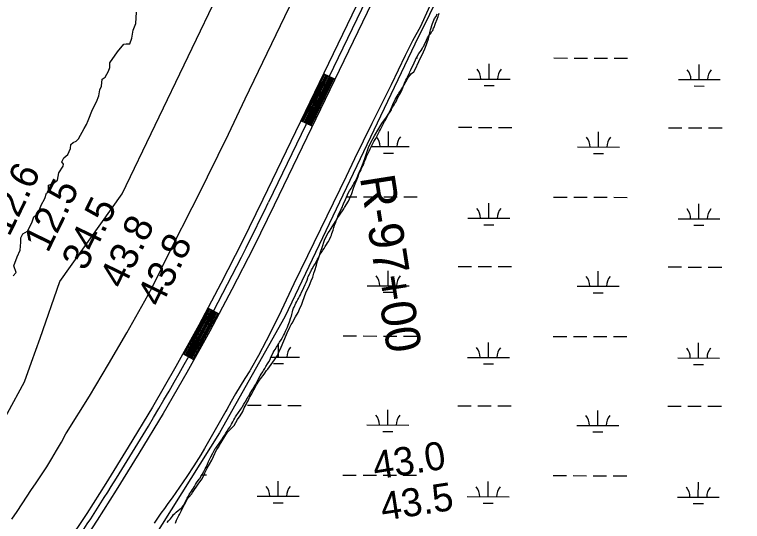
# Model space of a CAD drawing. Extents: x 3180038 to 3217926, y 922069 to 947485.
# Drawn here: x 3189237 to 3190976, y 935548 to 936760 of the extents above; entities that cross this region are included whole.
import ezdxf

# ---------------------------------------------------------------- set-up
doc = ezdxf.new("R2010")
doc.units = 0
for name, color, linetype in [('V-LEVE-TOET', 7, 'Continuous'), ('V-RIVR-EDGE', 7, 'Continuous'), ('V-RIVR-RANG', 7, 'Continuous'), ('V-RIVR-RANG-IDEN', 7, 'Continuous'), ('V-ROAD-CNTR', 7, 'Continuous'), ('V-SITE-VEGE', 7, 'Continuous'), ('V-TOPO-SHOR', 7, 'Continuous'), ('V-WETL-SWMP', 7, 'Continuous')]:
    doc.layers.add(name, color=color, linetype=linetype)

msp = doc.modelspace()

# ---------------------------------------------------------------- linework, layer by layer
at = {"layer": 'V-LEVE-TOET'}
for points in [[(3189230.6, 935554.3), (3189243.1, 935572.3), (3189255.3, 935590.5), (3189267.1, 935608.9), (3189275.5, 935622.2), (3189275.5, 935622.2), (3189288.5, 935641), (3189301.2, 935660), (3189313.5, 935679.2), (3189325.6, 935698.6), (3189337.2, 935718.2), (3189348.6, 935738.1), (3189359.6, 935758.1), (3189360.7, 935760.2), (3189360.7, 935760.2), (3189415.5, 935847.9), (3189461.5, 935924), (3189461.5, 935924), (3189505.4, 935999.3), (3189548, 936075.4), (3189565.3, 936107.2), (3189565.3, 936107.2), (3189612.4, 936203.2), (3189661.1, 936298.5), (3189673.2, 936321.5), (3189673.2, 936321.5), (3189747.7, 936474), (3189787.7, 936558.6), (3189787.7, 936558.6), (3189903.7, 936800.3)], [(3190229, 936780.3), (3190216.9, 936754.5), (3190206.3, 936731.3), (3190206.3, 936731.3), (3190187.9, 936696.8), (3190170.1, 936662.1), (3190152.9, 936627), (3190136.3, 936591.6), (3190132.9, 936584.2), (3190132.9, 936584.2), (3190090.2, 936499.8), (3190049.1, 936414.6), (3190029.4, 936372.6), (3190029.4, 936372.6), (3189936.3, 936183.2), (3189936.3, 936183.2), (3189904.1, 936116.6), (3189873.9, 936051.6), (3189873.9, 936051.6), (3189856.3, 936015.6), (3189838.1, 935980), (3189819.2, 935944.7), (3189799.8, 935909.7), (3189799, 935908.3), (3189799, 935908.3), (3189787.3, 935890.2), (3189776, 935871.9), (3189765, 935853.4), (3189754.3, 935834.7), (3189743.9, 935815.8), (3189741.9, 935811.9), (3189741.9, 935811.9), (3189690.7, 935723.1), (3189681.6, 935707.6), (3189681.6, 935707.6), (3189665.1, 935681.6), (3189648.3, 935655.8), (3189630.9, 935630.3), (3189613.2, 935605.1), (3189603.2, 935591.3), (3189603.2, 935591.3), (3189594.7, 935579.7), (3189586.4, 935568), (3189578.3, 935556.2), (3189570.5, 935544.2)]]:
    msp.add_lwpolyline(points, dxfattribs=at)
at = {"layer": 'V-RIVR-EDGE'}
for points in [[(3189383.8, 936457.4), (3189389.6, 936463.1), (3189403.1, 936487.5), (3189408.8, 936496.8), (3189412.5, 936506.6), (3189422.9, 936532.5), (3189432.3, 936551.2), (3189438, 936565.2), (3189440.2, 936579.7), (3189444.3, 936588.5), (3189446.4, 936605.6), (3189453.2, 936610.2), (3189461.5, 936624.2), (3189464.7, 936633.6), (3189464.7, 936644.4), (3189482.4, 936670.3), (3189497.5, 936689), (3189503.2, 936690), (3189512, 936690), (3189517.2, 936703.4), (3189519.9, 936722.1), (3189526.6, 936738.2), (3189528.3, 936765.1)], [(3189233.2, 936135.2), (3189241, 936143), (3189235.3, 936159.1), (3189243.1, 936180.8), (3189250.4, 936196.9), (3189251.5, 936215.6), (3189251.5, 936225.9), (3189256.2, 936235.8), (3189267.7, 936242), (3189278.1, 936262.2), (3189282.8, 936276.2), (3189293.2, 936284.4), (3189300.5, 936304.1), (3189309.3, 936320.2), (3189313, 936332.6), (3189317.7, 936336.2), (3189317.7, 936345.6), (3189317.7, 936352.3), (3189329.1, 936355.9), (3189339, 936364.2), (3189342.7, 936381.8), (3189352.6, 936397.3), (3189353.6, 936402.5), (3189350, 936408.2), (3189354.2, 936417.6), (3189364.1, 936425.3), (3189370.8, 936439.3), (3189371.4, 936449.2), (3189376.6, 936453.8), (3189383.8, 936457.4)]]:
    msp.add_lwpolyline(points, dxfattribs=at)
at = {"layer": 'V-ROAD-CNTR'}
for p, q in [((3190001.8, 936605.2), (3189974.8, 936618.3)), ((3189947.5, 936492.7), (3189920.5, 936505.7)), ((3189724.9, 936044.3), (3189698.4, 936058.5)), ((3189665.1, 935934.4), (3189638.8, 935948.8))]:
    msp.add_line(p, q, dxfattribs=at)
for points in [[(3191151.8, 939057.1), (3189829.7, 936317.7), (3189780.6, 936216.3), (3189729.6, 936116.7), (3189676.7, 936017.8), (3189622.4, 935919), (3189566.1, 935821.9), (3189508.3, 935726.2), (3189454.5, 935639.5), (3189409.3, 935567.6), (3189362.7, 935497.1), (3189314.9, 935427.3), (3189266, 935357.7), (3189215.7, 935289.5), (3189180.7, 935243.5), (3188970.6, 934976.4)], [(3191178.2, 939042.8), (3189856.7, 936304.6), (3189807.5, 936202.9), (3189756.2, 936102.8), (3189703.1, 936003.5), (3189648.6, 935904.3), (3189592, 935806.6), (3189533.9, 935710.5), (3189479.9, 935623.6), (3189434.5, 935551.3), (3189387.6, 935480.3), (3189339.5, 935410.2), (3189290.3, 935340.2), (3189239.7, 935271.6), (3189204.5, 935225.2)], [(3191165, 939050), (3189843.2, 936311.1)], [(3189977.5, 936617), (3189923.2, 936504.4)], [(3189980.2, 936615.7), (3189925.9, 936503.1)], [(3189982.9, 936614.4), (3189928.6, 936501.8)], [(3189985.6, 936613.1), (3189931.3, 936500.5)], [(3189988.3, 936611.8), (3189934, 936499.2)], [(3189991, 936610.4), (3189936.7, 936497.9)], [(3189993.7, 936609.1), (3189939.4, 936496.6)], [(3189996.4, 936607.8), (3189942.1, 936495.3)], [(3189999.1, 936606.5), (3189944.8, 936494)], [(3189701.1, 936057), (3189679.4, 936016.4), (3189641.4, 935947.4)], [(3189703.7, 936055.6), (3189682, 936015), (3189644.1, 935945.9)], [(3189706.4, 936054.2), (3189684.6, 936013.5), (3189646.7, 935944.5)], [(3189709, 936052.8), (3189687.3, 936012.1), (3189649.3, 935943)], [(3189711.7, 936051.4), (3189689.9, 936010.7), (3189652, 935941.6)], [(3189714.3, 936050), (3189692.5, 936009.3), (3189654.6, 935940.1)], [(3189717, 936048.6), (3189695.2, 936007.8), (3189657.2, 935938.7)], [(3189719.6, 936047.1), (3189697.8, 936006.4), (3189659.8, 935937.2)], [(3189722.3, 936045.7), (3189700.5, 936005), (3189662.5, 935935.8)]]:
    msp.add_lwpolyline(points, dxfattribs=at)
for centre, radius, start, end in [((3184024.3, 939087.2), 6447.3, 327.58963, 334.4957), ((3185329.5, 938198.4), 4869.2, 322.5019, 328.187)]:
    msp.add_arc(centre, radius, start, end, dxfattribs=at)
at = {"layer": 'V-SITE-VEGE'}
for points in [[(3190064.7, 936392.3), (3190069.6, 936405), (3190075.4, 936420.3), (3190080.3, 936434.7), (3190082.7, 936442.4), (3190087.6, 936454.3), (3190096.8, 936469.6), (3190106.7, 936487.5), (3190111.7, 936495.2), (3190114.1, 936499.4), (3190115.8, 936502), (3190125.8, 936514.8), (3190130.8, 936523.3), (3190136.5, 936535.2), (3190140.6, 936544.6), (3190146.4, 936556.5), (3190153, 936568.4), (3190154.7, 936571.8), (3190159.7, 936578.6), (3190164.6, 936586.3), (3190167.9, 936592.2), (3190171.2, 936599), (3190176.2, 936607.6), (3190177.9, 936610.1), (3190185.4, 936618.7), (3190190.4, 936623), (3190193.7, 936628.1), (3190202.8, 936647.6), (3190206.1, 936654.4), (3190211, 936663.8), (3190213.5, 936670.6), (3190216.8, 936678.2), (3190218.4, 936681.6), (3190225.8, 936702), (3190228.2, 936712.2), (3190229.8, 936719.8), (3190230.6, 936723.2), (3190235.5, 936738.5), (3190240.4, 936750.4), (3190243.7, 936755.5), (3190246.2, 936761.5)], [(3189621.2, 935544.6), (3189623.6, 935551.4), (3189629.4, 935562.5), (3189631.1, 935565), (3189635.2, 935572.7), (3189636, 935575.3), (3189642.6, 935588.9), (3189645.9, 935594.8), (3189649.2, 935601.6), (3189653.4, 935606.8), (3189660.1, 935614.4), (3189661.7, 935617.8), (3189675.8, 935637.5), (3189684.1, 935649.4), (3189689.1, 935657.9), (3189691.6, 935664.7), (3189697.3, 935675.8), (3189708.1, 935694.5), (3189712.2, 935703.9), (3189719.6, 935719.2), (3189724.6, 935726.9), (3189726.3, 935731.1), (3189745.3, 935761.8), (3189761.2, 935778), (3189769.5, 935791.7), (3189776.1, 935801.1), (3189781.9, 935811.3), (3189785.2, 935819.8), (3189790.2, 935828.3), (3189791.8, 935831.7), (3189795.1, 935836.8), (3189798.4, 935844.5), (3189803.4, 935853.8), (3189805, 935856.4), (3189808.3, 935863.2), (3189814.9, 935875.1), (3189821.6, 935886.2), (3189824.1, 935889.6), (3189833.2, 935900.7), (3189839, 935909.2), (3189841.5, 935912.6), (3189858.2, 935934.8), (3189864.8, 935945), (3189868.1, 935952.7), (3189873.9, 935964.6), (3189880.4, 935979.9), (3189886.2, 935995.2), (3189889.5, 936002.8), (3189892.8, 936008.8), (3189894.4, 936013.1), (3189897.7, 936019), (3189900.2, 936022.4), (3189907.6, 936037.7), (3189914.3, 936048), (3189917.6, 936055.6), (3189923.3, 936067.5), (3189925.8, 936075.2), (3189932.3, 936094.7), (3189941.4, 936113.4), (3189945.5, 936123.6), (3189949.6, 936132.1), (3189952, 936141.4), (3189954.5, 936148.2), (3189958.5, 936161), (3189960.9, 936170.3), (3189963.4, 936178.8), (3189968.3, 936194.1), (3189971.5, 936203.4), (3189977.2, 936220.4), (3189978.9, 936224.6), (3189986.3, 936238.3), (3189989.6, 936242.5), (3189993, 936248.5), (3190003.7, 936265.5), (3190007.9, 936272.3), (3190012.9, 936280), (3190023.7, 936295.4), (3190025.3, 936298.8), (3190034.4, 936314.1), (3190036.9, 936319.2), (3190039.4, 936325.2), (3190041, 936328.6), (3190041.8, 936329.4), (3190047.5, 936347.2), (3190057.4, 936372.7), (3190060.6, 936384.6), (3190064.7, 936392.3)]]:
    msp.add_lwpolyline(points, dxfattribs=at)
at = {"layer": 'V-TOPO-SHOR'}
for points in [[(3190415.2, 937099.5), (3190388.9, 937087.8), (3190378.7, 937064.2), (3190368.6, 937043.9), (3190192.9, 936689.2), (3189882.2, 936037.3), (3189726.8, 935760.3), (3189520.7, 935432.6), (3189334.9, 935169.2), (3189399.1, 935172.5), (3189476.8, 935067.8), (3189524.1, 934946.2), (3189571.4, 934865.1), (3189625.5, 934824.6), (3189672.7, 934790.8), (3189730.2, 934743.5), (3189740.3, 934652.3), (3189747.1, 934473.3), (3189751.4, 934371.1)], [(3188341.8, 934753.7), (3188666.1, 935142.1), (3188757.3, 935230), (3188821.5, 935287.4), (3188892.4, 935334.7), (3188933, 935388.7), (3188987, 935473.2), (3189108.6, 935625.2), (3189179.6, 935740), (3189220.1, 935807.6), (3189260.6, 935881.9), (3189277.5, 935929.2), (3189297.8, 935986.6), (3189345.1, 936121.7), (3189493.7, 936331.2), (3189730.2, 936824.4)]]:
    msp.add_lwpolyline(points, dxfattribs=at)
at = {"layer": 'V-WETL-SWMP'}
for p, q in [((3190197.1, 936656.7), (3190199.6, 936656.7)), ((3190370.8, 936605.6), (3190370.8, 936641.6)), ((3190525.5, 936656), (3190557.5, 936655.9)), ((3190573.5, 936655.9), (3190605.5, 936655.8)), ((3190621.5, 936655.8), (3190653.5, 936655.7)), ((3190669.5, 936655.7), (3190701.5, 936655.6)), ((3190872.7, 936604.5), (3190872.7, 936640.5)), ((3190320.8, 936605.7), (3190420.8, 936605.5)), ((3190358.7, 936590.2), (3190382.7, 936590.1)), ((3190822.7, 936604.6), (3190922.7, 936604.4)), ((3190860.6, 936589.1), (3190884.6, 936589)), ((3190297.1, 936490.3), (3190329.1, 936490.3)), ((3190345.1, 936490.2), (3190377.1, 936490.2)), ((3190393.1, 936490.1), (3190425.1, 936490)), ((3190799, 936489.2), (3190831, 936489.1)), ((3190847, 936489.1), (3190879, 936489)), ((3190895, 936489), (3190927, 936488.9)), ((3190129.9, 936444.3), (3190130, 936480.3)), ((3190631.8, 936443.2), (3190631.9, 936479.2)), ((3190089.2, 936444.4), (3190179.9, 936444.2)), ((3190581.8, 936443.3), (3190681.8, 936443)), ((3190117.9, 936428.9), (3190141.9, 936428.8)), ((3190619.8, 936427.7), (3190643.8, 936427.7)), ((3190030.2, 936324.4), (3190054.8, 936324.4)), ((3190070.8, 936324.3), (3190102.8, 936324.3)), ((3190118.8, 936324.2), (3190150.8, 936324.2)), ((3190166.8, 936324.1), (3190198.8, 936324.1)), ((3190524.7, 936323.3), (3190556.7, 936323.3)), ((3190572.7, 936323.2), (3190604.7, 936323.1)), ((3190620.7, 936323.1), (3190652.7, 936323)), ((3190668.7, 936323), (3190700.7, 936322.9)), ((3190370, 936272.9), (3190370.1, 936308.9)), ((3190871.9, 936271.8), (3190872, 936307.8)), ((3190320, 936273), (3190420, 936272.8)), ((3190821.9, 936271.9), (3190921.9, 936271.7)), ((3190358, 936257.5), (3190382, 936257.5)), ((3190859.9, 936256.4), (3190883.9, 936256.3)), ((3190296.3, 936157.7), (3190328.3, 936157.6)), ((3190344.3, 936157.6), (3190376.3, 936157.5)), ((3190392.3, 936157.5), (3190424.3, 936157.4)), ((3190798.2, 936156.5), (3190830.2, 936156.5)), ((3190846.2, 936156.4), (3190878.2, 936156.4)), ((3190894.2, 936156.3), (3190926.2, 936156.3)), ((3190129.2, 936111.6), (3190129.2, 936147.6)), ((3190631.1, 936110.5), (3190631.1, 936146.5)), ((3190079.2, 936111.7), (3190179.2, 936111.5)), ((3190581.1, 936110.6), (3190681.1, 936110.4)), ((3190117.1, 936096.2), (3190141.1, 936096.2)), ((3190619, 936095.1), (3190643, 936095)), ((3190022, 935991.8), (3190054, 935991.7)), ((3190070, 935991.7), (3190102, 935991.6)), ((3190118, 935991.6), (3190150, 935991.5)), ((3190166, 935991.5), (3190198, 935991.4)), ((3190523.9, 935990.7), (3190555.9, 935990.6)), ((3190571.9, 935990.6), (3190603.9, 935990.5)), ((3190619.9, 935990.4), (3190651.9, 935990.4)), ((3190667.9, 935990.3), (3190699.9, 935990.3)), ((3189867.3, 935941.4), (3189867.4, 935972.8)), ((3190369.2, 935940.3), (3190369.3, 935976.3)), ((3190871.1, 935939.1), (3190871.2, 935975.1)), ((3189849.6, 935941.4), (3189917.3, 935941.3)), ((3190319.2, 935940.4), (3190419.2, 935940.2)), ((3190821.1, 935939.3), (3190921.1, 935939)), ((3189855.3, 935926), (3189879.3, 935925.9)), ((3190357.2, 935924.9), (3190381.2, 935924.8)), ((3190859.1, 935923.7), (3190883.1, 935923.7)), ((3189793.7, 935826.1), (3189825.7, 935826.1)), ((3189841.7, 935826), (3189873.7, 935826)), ((3189889.7, 935825.9), (3189921.7, 935825.9)), ((3190295.6, 935825), (3190327.6, 935824.9)), ((3190343.6, 935824.9), (3190375.6, 935824.8)), ((3190391.6, 935824.8), (3190423.6, 935824.7)), ((3190797.5, 935823.9), (3190829.5, 935823.8)), ((3190128.4, 935779), (3190128.5, 935815)), ((3190630.3, 935777.8), (3190630.4, 935813.8)), ((3190845.5, 935823.8), (3190877.5, 935823.7)), ((3190893.5, 935823.7), (3190925.5, 935823.6)), ((3190078.4, 935779.1), (3190178.4, 935778.8)), ((3190580.3, 935777.9), (3190680.3, 935777.7)), ((3190116.4, 935763.6), (3190140.4, 935763.5)), ((3190618.3, 935762.4), (3190642.3, 935762.4)), ((3189684.2, 935659.9), (3189695.4, 935659.9)), ((3190021.3, 935659.1), (3190053.3, 935659.1)), ((3190069.3, 935659), (3190101.3, 935659)), ((3190117.3, 935658.9), (3190149.3, 935658.8)), ((3190165.3, 935658.8), (3190197.3, 935658.7)), ((3190523.2, 935658), (3190555.2, 935657.9)), ((3190571.2, 935657.9), (3190603.2, 935657.8)), ((3190619.2, 935657.8), (3190651.2, 935657.7)), ((3190667.2, 935657.7), (3190699.2, 935657.6)), ((3189866.6, 935608.7), (3189866.7, 935644.7)), ((3190368.5, 935607.6), (3190368.6, 935643.6)), ((3190870.4, 935606.5), (3190870.5, 935642.5)), ((3189816.6, 935608.9), (3189916.6, 935608.6)), ((3190318.5, 935607.7), (3190418.5, 935607.5)), ((3190820.4, 935606.6), (3190920.4, 935606.4)), ((3189854.5, 935593.3), (3189878.5, 935593.3)), ((3190356.4, 935592.2), (3190380.4, 935592.2)), ((3190858.4, 935591.1), (3190882.4, 935591))]:
    msp.add_line(p, q, dxfattribs=at)
for points in [[(3190237.9, 936727.1), (3190239.9, 936730.8), (3190241.1, 936734.4), (3190242.6, 936738.9), (3190246.5, 936749), (3190248.9, 936755.1), (3190249.6, 936758.3), (3190251.2, 936762.8)], [(3190001.5, 936256.1), (3190003.4, 936261), (3190005.4, 936267.1), (3190006.5, 936270.3), (3190008.1, 936273.6), (3190010, 936280.4), (3190012.8, 936285.7), (3190017.9, 936296.3), (3190020.3, 936300.3), (3190021, 936303.6), (3190022.6, 936307.6), (3190027.3, 936317.7), (3190029.7, 936323.4), (3190032, 936328.7), (3190034, 936332.7), (3190037.1, 936338.4), (3190039.1, 936341.3), (3190040.7, 936344.1), (3190042.3, 936347), (3190045.8, 936353.1), (3190047.4, 936356.3), (3190050.2, 936360.8), (3190052.1, 936363.6), (3190054.1, 936367.3), (3190055.3, 936370.5), (3190056.8, 936374.2), (3190058, 936377), (3190062.8, 936384.7), (3190064.7, 936388.8), (3190065.9, 936391.6), (3190067.5, 936395.7), (3190069.4, 936399.3), (3190071.8, 936405.4), (3190072.9, 936409), (3190074.9, 936413.1), (3190077.6, 936420.4), (3190080, 936425.6), (3190081.6, 936428.5), (3190083.9, 936433.4), (3190086.7, 936439), (3190088.6, 936443.5), (3190095.3, 936456.5), (3190098.1, 936460.9), (3190099.7, 936463.8), (3190102.4, 936468.7), (3190106, 936476), (3190108.3, 936480.8), (3190110.7, 936485.3), (3190113.5, 936489.8), (3190115.8, 936494.6), (3190118.6, 936499.1), (3190120.9, 936504.4), (3190122.9, 936507.6), (3190124.9, 936511.3), (3190130.4, 936521.8), (3190134, 936527.1), (3190137.1, 936532), (3190138.3, 936535.6), (3190139.9, 936538.5), (3190141.9, 936541.3), (3190143.4, 936544.2), (3190145.4, 936548.2), (3190147.4, 936550.7), (3190150.1, 936556.3), (3190152.5, 936561.2), (3190155.7, 936566.9), (3190158.8, 936571.8), (3190160.4, 936575), (3190162.7, 936580.7), (3190164.3, 936584.7), (3190165.9, 936589.6), (3190167.8, 936593.6), (3190168.6, 936596.9), (3190171.3, 936602.6), (3190173.7, 936607), (3190175.3, 936609.9), (3190176.5, 936612.7), (3190180.4, 936619.6), (3190181.2, 936622.8), (3190183.5, 936627.3), (3190186.3, 936633.4), (3190189.8, 936640.7), (3190191.8, 936644.7), (3190194.5, 936651.2), (3190195.7, 936654.1), (3190198.4, 936659.7), (3190202.8, 936666.6), (3190205.6, 936670.7), (3190207.9, 936674), (3190210.3, 936677.6), (3190212.3, 936681.7), (3190214.3, 936684.5), (3190215.8, 936688.6), (3190219.8, 936696.3), (3190221.7, 936700.7), (3190223.7, 936704.4), (3190228.5, 936710.9), (3190230.4, 936713.7), (3190234, 936719), (3190236, 936721.9), (3190237.9, 936727.1)], [(3189767.6, 935802.9), (3189770, 935806.2), (3189773.5, 935811.1), (3189775.5, 935814.3), (3189777.5, 935816.8), (3189779.5, 935819.6), (3189781.5, 935823.3), (3189784.6, 935828.9), (3189787.8, 935833.4), (3189789.4, 935836.7), (3189793.7, 935844), (3189795.3, 935846.8), (3189797.3, 935849.7), (3189799.2, 935853.7), (3189802, 935858.2), (3189804.4, 935861.8), (3189805.9, 935864.7), (3189809.5, 935870.4), (3189812.3, 935875.2), (3189815.4, 935880.9), (3189817, 935884.6), (3189819.7, 935889.4), (3189823.3, 935896.3), (3189825.7, 935900.4), (3189829.6, 935906.1), (3189831.6, 935909.3), (3189834.8, 935914.2), (3189837.5, 935918.7), (3189841.1, 935924.8), (3189844.6, 935930.1), (3189847.4, 935935.7), (3189849.3, 935941), (3189853.3, 935948.3), (3189854.9, 935952), (3189856.8, 935956), (3189859.2, 935959.3), (3189862.4, 935964.6), (3189863.9, 935967.4), (3189865.5, 935970.2), (3189867.9, 935973.5), (3189869.9, 935977.1), (3189873.8, 935982.4), (3189877, 935987.7), (3189879.3, 935992.6), (3189881.7, 935996.6), (3189884.1, 936003.1), (3189885.6, 936006), (3189887.2, 936009.6), (3189888.8, 936012.9), (3189890.7, 936017.7), (3189893.8, 936025.8), (3189896.6, 936035.5), (3189898.1, 936039.2), (3189898.9, 936042.8), (3189900.8, 936049.3), (3189902, 936053.3), (3189903.1, 936057.8), (3189904.7, 936060.6), (3189909, 936070.4), (3189911, 936074.4), (3189913.8, 936078.5), (3189914.9, 936081.3), (3189917.7, 936086.2), (3189919.7, 936090.2), (3189922.4, 936096.3), (3189925.2, 936101.6), (3189927.9, 936107.7), (3189931, 936114.6), (3189933.4, 936119.4), (3189935.8, 936125.1), (3189937.3, 936130.4), (3189938.5, 936134), (3189941.2, 936139.3), (3189943.2, 936142.5), (3189944.8, 936146.2), (3189945.2, 936147), (3189946.3, 936149.4), (3189947.9, 936152.3), (3189951.9, 936159.2), (3189955.4, 936164.9), (3189957.4, 936168.9), (3189959.4, 936171.8), (3189960.9, 936175.4), (3189962.9, 936178.3), (3189964.1, 936181.1), (3189966.8, 936186.8), (3189969.2, 936190), (3189971.6, 936193.7), (3189973.6, 936196.5), (3189976.3, 936201), (3189979.1, 936205.5), (3189982.3, 936210.4), (3189984.6, 936214), (3189986.6, 936217.7), (3189989.4, 936222.1), (3189992.1, 936229), (3189993.7, 936232.7), (3189994.4, 936236.7), (3189997.6, 936244.4), (3189999.5, 936250.5), (3190001.5, 936256.1)], [(3189601.1, 935545.7), (3189604.2, 935549.7), (3189606.6, 935552.6), (3189609, 935555), (3189613.8, 935561.1), (3189616.9, 935565.2), (3189619.3, 935567.3), (3189622.5, 935570.9), (3189627.3, 935574.6), (3189631.7, 935577.9), (3189634.9, 935579.9), (3189637.3, 935582.4), (3189640.5, 935586.5), (3189642, 935589.7), (3189644.4, 935594.6), (3189647.2, 935599.9), (3189649.5, 935604.3), (3189652.3, 935609.2), (3189654.2, 935612.8), (3189659.4, 935621), (3189662.2, 935625), (3189664.1, 935627.9), (3189666.9, 935631.9), (3189669.3, 935636.4), (3189671.6, 935640.5), (3189678, 935649.4), (3189680, 935651.9), (3189681.9, 935655.5), (3189684.7, 935660.8), (3189688.6, 935667.7), (3189692.2, 935673.8), (3189694.6, 935678.2), (3189698.1, 935685.5), (3189700.4, 935691.6), (3189702.8, 935696.1), (3189704, 935699.3), (3189705.5, 935703), (3189710.3, 935711.5), (3189714.6, 935719.6), (3189716.2, 935722.5), (3189718.2, 935725.3), (3189721.3, 935729.4), (3189725.3, 935735.1), (3189728.5, 935739.5), (3189731.2, 935744), (3189733.2, 935746.9), (3189735.2, 935749.3), (3189738.4, 935753.8), (3189741.5, 935759.1), (3189744.7, 935763.9), (3189746.7, 935767.2), (3189749.1, 935770.4), (3189751.8, 935774.5), (3189755.4, 935781), (3189756.6, 935783.4), (3189756.5, 935783.8), (3189758.1, 935786.7), (3189760.5, 935791.5), (3189762.9, 935795.6), (3189764.8, 935798.5), (3189767.6, 935802.9)]]:
    msp.add_lwpolyline(points, dxfattribs=at)
for centre, start, end in [((3190315.5, 936606.2), 359.099, 40.6427), ((3190426, 936605.9), 139.099, 180.6426), ((3190817.4, 936605.1), 359.099, 40.6427), ((3190927.9, 936604.8), 139.099, 180.6426), ((3190074.7, 936444.9), 359.099, 39.7052), ((3190185.2, 936444.6), 139.099, 180.6426), ((3190576.6, 936443.8), 359.099, 40.6427), ((3190687.1, 936443.5), 139.099, 180.6426), ((3190314.8, 936273.5), 359.099, 40.6427), ((3190425.2, 936273.3), 139.099, 180.6426), ((3190816.7, 936272.4), 359.099, 40.6427), ((3190927.1, 936272.2), 139.099, 180.6426), ((3190073.9, 936112.2), 359.099, 40.6427), ((3190184.4, 936112), 139.099, 180.6426), ((3190575.8, 936111.1), 359.099, 40.6427), ((3190686.3, 936110.8), 139.099, 180.6426), ((3189922.6, 935941.8), 139.099, 180.6426), ((3190314, 935940.9), 359.099, 40.6427), ((3190424.5, 935940.6), 139.099, 180.6426), ((3190815.9, 935939.7), 359.099, 40.6427), ((3190926.4, 935939.5), 139.099, 180.6426), ((3190073.2, 935779.6), 359.099, 40.6427), ((3190183.6, 935779.3), 139.099, 180.6426), ((3190575.1, 935778.4), 359.099, 40.6427), ((3190685.6, 935778.2), 139.099, 180.6426), ((3189811.3, 935609.3), 359.099, 40.6427), ((3189921.8, 935609.1), 139.099, 180.6426), ((3190313.2, 935608.2), 359.099, 40.6427), ((3190423.7, 935608), 139.099, 180.6426), ((3190815.1, 935607.1), 359.099, 40.6427), ((3190925.6, 935606.8), 139.099, 180.6426)]:
    msp.add_arc(centre, 35.2, start, end, dxfattribs=at)

# ---------------------------------------------------------------- texts
at = {"layer": 'V-RIVR-RANG'}
for s, rotation, p in [('-12.6', 64.0783, (3189210.9, 936200.1)), ('12.5', 64.0783, (3189316.3, 936188.2)), ('34.5', 64.0783, (3189406.3, 936144.7)), ('43.8', 64.0783, (3189496.4, 936101.2)), ('43.8', 64.0783, (3189586.4, 936057.7)), ('43.0', 8.7983, (3190098, 935648.3)), ('43.5', 8.7983, (3190116.5, 935549.9))]:
    msp.add_text(s, height=67, rotation=rotation, dxfattribs=at).set_placement(p)
at = {"layer": 'V-RIVR-RANG-IDEN'}
msp.add_text('R-97+00', height=83, rotation=278.938, dxfattribs=at).set_placement((3190061.7, 936370.8))

doc.saveas('drawing.dxf')
